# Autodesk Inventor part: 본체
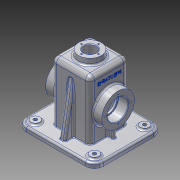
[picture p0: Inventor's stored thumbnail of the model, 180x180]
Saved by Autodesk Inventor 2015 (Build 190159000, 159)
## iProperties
Created: 2016-02
Part Number: 본체
Material: 알루미늄 6061
Document SubType Name: Modeling
Designer: Administrator
Density: 2.7 g/cm^3
Appearance: 알루미늄 - 평지
Mass: 804.638 g
Surface Area: 910.774 cm^2
Volume: 298.014 cm^3
Author: Administrator
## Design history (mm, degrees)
sketch "스케치1"
  geometry: L1 (-65, 57.5)-(65, 57.5); L2 (65, 57.5)-(65, -57.5); L3 (65, -57.5)-(-65, -57.5); L4 (-65, -57.5)-(-65, 57.5); L5 (-65, 57.5)-(65, -57.5); L6 (65, 57.5)-(-65, -57.5); 1 further point
  constraints: 12 end point, 2 midpoint, 2 parallel, 1 horizontal, 1 perpendicular
  dimensions: "d0" = 115 distance of L1.end L2.end; "d1" = 130 distance of L1.start L1.end
extrude "돌출1" new body sketch "스케치1" distance "d2" = 8; taper "d3" = 0 deg
sketch "스케치2"
  geometry: L1 (-32.5, 32.5)-(32.5, 32.5); L2 (32.5, 32.5)-(32.5, -32.5); L3 (32.5, -32.5)-(-32.5, -32.5); L4 (-32.5, -32.5)-(-32.5, 32.5); L5 (-32.5, 32.5)-(32.5, -32.5); L6 (32.5, 32.5)-(-32.5, -32.5); 1 further point
  constraints: 12 end point, 2 midpoint, 2 parallel, 1 horizontal, 1 perpendicular
  dimensions: "d4" = 65 distance of L1.start L1.end; "d5" = 65 distance of L1.end L2.end
extrude "돌출2" join sketch "스케치2" distance "d6" = 100; taper "d7" = 0 deg
sketch "스케치3"
  geometry: L1 (65, 57.5)-(-65, 57.5) reference; L2 (-5, -47.5)-(5, -47.5); L3 (5, -47.5)-(5, 47.5); L4 (5, 47.5)-(-5, 47.5); L5 (-5, 47.5)-(-5, -47.5); L6 (-5, -47.5)-(5, 47.5); L7 (5, -47.5)-(-5, 47.5); 1 further point
  constraints: 12 end point, 2 midpoint, 2 parallel, 1 horizontal, 1 perpendicular
  dimensions: "d8" = 10 distance of L3.end L4.end; "d9" = 10 distance between parallel lines of L1 L4
extrude "돌출3" join sketch "스케치3" distance "d10" = 100; taper "d11" = 0 deg
feature "면 기울기1" dims angle "d12" = 10 deg
sketch "스케치4"
  geometry: L1 (42.5, -3)-(-42.5, -3); L2 (-42.5, -3)-(-42.5, 3); L3 (-42.5, 3)-(42.5, 3); L4 (42.5, 3)-(42.5, -3); L5 (42.5, -3)-(-42.5, 3); L6 (-42.5, -3)-(42.5, 3); 1 further point
  constraints: 12 end point, 2 midpoint, 2 parallel, 1 horizontal, 1 perpendicular
  dimensions: "d13" = 6 distance of L3.end L1.start; "d14" = 85 distance of L1.start L1.end
extrude "돌출4" join sketch "스케치4" distance "d15" = 55; taper "d16" = 0 deg
sketch "스케치5"
  geometry: C1 r 20 at (0, 0); 1 further point
  constraints: 1 centre point, 1 coincident
  dimensions: "d17" = 40 diameter of C1
extrude "돌출5" join sketch "스케치5" distance "d18" = 10; taper "d19" = 0 deg
sketch "스케치7"
  geometry: L1 (65, 57.5)-(-65, 57.5) reference; L2 (-65, 57.5)-(-65, -57.5) reference; L3 (-65, -57.5)-(65, -57.5) reference; L4 (65, -57.5)-(65, 57.5) reference; L5 (60, -52.5)-(-60, -52.5); L6 (-60, -52.5)-(-60, 52.5); L7 (-60, 52.5)-(60, 52.5); L8 (60, 52.5)-(60, -52.5); 1 further point
  constraints: 8 end point, 3 other
  dimensions: "d21" = 5 distance between parallel lines of L3 L5
extrude "돌출6" join sketch "스케치7" distance "d22" = 2; taper "d23" = 0 deg
sketch "스케치9"
  geometry: L1 (-65, -57.5)-(65, -57.5) reference; L2 (65, -57.5)-(65, 57.5) reference; C1 r 7.5 at (50, -42.5); 1 further point
  constraints: 1 centre point
  dimensions: "d36" = 15 diameter of C1; "d37" = 15 distance from line of L1 C1.centre; "d38" = 15 distance from line of L2 C1.centre
extrude "돌출8" join sketch "스케치9" distance "d39" = 3; taper "d40" = 0 deg
hole "구멍1" diameter "d49" = 6; stored, may be unused: countersink angle "d53" = 90 deg, drill point angle "d55" = 118 deg; dims "d47" = 10, "d48" = 10, "d50" = 6, "d51" = 4, "d52" = 2, "d54" = 8
hole "구멍2" diameter "d58" = 6; stored, may be unused: countersink angle "d62" = 90 deg, drill point angle "d64" = 118 deg; dims "d56" = 10, "d57" = 10, "d59" = 6, "d60" = 4, "d61" = 2, "d63" = 8
hole "구멍3" diameter "d67" = 6; stored, may be unused: countersink angle "d71" = 90 deg, drill point angle "d73" = 118 deg; dims "d65" = 10, "d66" = 10, "d68" = 6, "d69" = 4, "d70" = 2, "d72" = 8
hole "구멍4" diameter "d76" = 6; stored, may be unused: countersink angle "d80" = 90 deg, drill point angle "d82" = 118 deg; dims "d74" = 10, "d75" = 10, "d77" = 6, "d78" = 4, "d79" = 2, "d81" = 8
sketch "스케치13"
  geometry: L1 (47.5, 8)-(57.5, 8) reference; L2 (57.5, 8)-(57.5, 0) reference; L3 (57.5, 0)-(52.5, 0) reference; L4 (52.5, 0)-(52.5, -2) reference; L5 (52.5, -2)-(-52.5, -2) reference; L6 (-52.5, -2)-(-52.5, 0) reference; L7 (-52.5, 0)-(-57.5, 0) reference; L8 (-57.5, 0)-(-57.5, 8) reference; L9 (-57.5, 8)-(-47.5, 8) reference; L10 (-47.5, 8)-(-32.5, 93.069) reference; L11 (-32.5, 93.069)-(-32.5, 108) reference; L12 (-32.5, 108)-(-20, 108) reference; L13 (-20, 108)-(-20, 118) reference; L14 (-20, 118)-(20, 118) reference; L15 (20, 118)-(20, 108) reference; L16 (20, 108)-(32.5, 108) reference; L17 (32.5, 108)-(32.5, 93.069) reference; L18 (32.5, 93.069)-(47.5, 8) reference; C1 r 27.5 at (0, 53); 1 further point
  constraints: 1 centre point, 1 vertical alignment
  dimensions: "d104" = 55 diameter of C1
extrude "돌출12" join sketch "스케치13" stored distance "d105" = 95; taper "d106" = 0 deg
sketch "스케치14"
  geometry: L1 (-52.379, 53)-(-27.5, 53); L2 (-27.5, 53)-(-27.5, 68); L3 (-27.5, 68)-(-30.5, 68); L4 (-30.5, 68)-(-30.5, 70.5); L5 (-30.5, 70.5)-(-52.379, 70.5); L6 (-52.379, 70.5)-(-52.379, 53); L7 (-60, -2)-(60, -2) reference; L8 (-32.5, 8)-(-32.5, 108) reference; 1 further point
  constraints: 12 end point, 5 perpendicular, 1 horizontal
  dimensions: "d107" = 55 distance between parallel lines of L7 L1; "d108" = 5 distance between parallel lines of L2 L8; "d109" = 3 distance of L2.end L3.end; "d111" = 30 diameter of L3 L1; "d112" = 35 diameter of L5 L1; "d113" = 19.87908 distance between parallel lines of L8 L6
revolve "회전2" sketch "스케치14" stored, may be unused: angle "d114" = 90 deg
sketch "스케치15"
  geometry: L1 (-27.5, 27.5)-(27.5, 27.5); L2 (27.5, 27.5)-(27.5, -27.5); L3 (27.5, -27.5)-(-27.5, -27.5); L4 (-27.5, -27.5)-(-27.5, 27.5); L5 (-27.5, 27.5)-(27.5, -27.5); L6 (27.5, 27.5)-(-27.5, -27.5); 1 further point
  constraints: 12 end point, 2 midpoint, 2 parallel, 1 horizontal, 1 perpendicular
  dimensions: "d115" = 55 distance of L1.end L2.end; "d116" = 55 distance of L1.start L1.end
extrude "돌출13" cut sketch "스케치15" distance "d117" = 105; taper "d118" = 0 deg
hole "구멍6" diameter "d121" = 21; stored, may be unused: countersink angle "d125" = 90 deg, drill point angle "d127" = 118 deg; dims "d119" = 10, "d120" = 10, "d122" = 6, "d123" = 4, "d124" = 2, "d126" = 8
sketch "스케치16"
  geometry: C1 r 17.5 at (0, 0) reference; 2 further points
  constraints: 1 horizontal alignment
  dimensions: "d128" = 21 distance of C1.centre point (-21, 0)
hole "구멍7" sketch "스케치16" at (-21, 0) diameter "d129" = 3.242; stored, may be unused: countersink angle "d133" = 90 deg, drill point angle "d135" = 118 deg; dims "d130" = 8, "d131" = 4, "d132" = 2, "d134" = 10
sketch "스케치17"
  geometry: C1 r 10.5 at (0, 0) reference; 1 further point
  constraints: 1 vertical alignment
  dimensions: "d139" = 14.5 distance of C1.centre point (0, -14.5)
hole "구멍8" sketch "스케치17" at (0, -14.5) diameter "d140" = 2.459; stored, may be unused: countersink angle "d144" = 90 deg, drill point angle "d146" = 118 deg; dims "d141" = 7, "d142" = 4, "d143" = 2, "d145" = 9
fillet "모깎기1" dims "d150" = 15
fillet "모깎기2" dims "d151" = 8
fillet "모깎기3" dims "d152" = 8
fillet "모깎기4" dims "d153" = 3
fillet "모깎기10" dims "d159" = 3
fillet "모깎기11" dims "d160" = 3
fillet "모깎기12" dims "d161" = 3
fillet "모깎기13" dims "d162" = 3
fillet "모깎기14" dims "d163" = 3
fillet "모깎기15" dims "d164" = 3
fillet "모깎기16" dims "d165" = 3
fillet "모깎기17" dims "d166" = 0.3
chamfer "모따기1" distance "d167" = 1; stored, may be unused: second distance "d168" = 2, angle "d169" = 45 deg
fillet "모깎기18" dims "d170" = 10
fillet "모깎기19" dims "d171" = 3
chamfer "모따기2" distance "d174" = 1; stored, may be unused: second distance "d175" = 2, angle "d176" = 45 deg
node "작업 평면2"
sketch "스케치19"
  geometry: L1 (20, 118)-(-20, 118) reference; 2 further points
  constraints: 1 vertical alignment, 1 other
  dimensions: "d179" = 26 distance from line of L1 point (0, 92)
feature "엠보싱1" sketch "스케치19" dims "d180" = 0.5, "d181" = 0
fillet "모깎기22" dims "d182" = 1
fillet "모깎기23" dims "d183" = 3
feature "면 기울기2" dims angle "d184" = 5 deg
fillet "모깎기24" dims "d185" = 3
fillet "모깎기25" dims "d186" = 3
node "솔리드1"
pattern_linear "직사각형 패턴1" dims "d43" = 100, "d46" = 85
mirror "대칭2"
pattern_circular "원형 패턴1" dims angle "d137" = 360 deg
mirror "대칭3"
pattern_circular "원형 패턴2" dims angle "d148" = 360 deg
node "절단 모서리 투영3"
other parameters: "d178" = 82.5
